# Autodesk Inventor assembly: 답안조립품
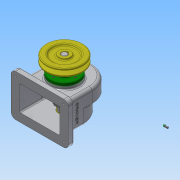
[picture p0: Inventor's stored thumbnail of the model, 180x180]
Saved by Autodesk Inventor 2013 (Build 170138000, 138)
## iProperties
Created: 2017-11
Part Number: 답안조립품
Document SubType Name: Assembly
Designer: Administrator
Author: Administrator
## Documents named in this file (14)
- C:\Users\Administrator\Desktop\471108V1012\답안조립품.iam
- C:\Users\Administrator\Desktop\471108V1012\본체.ipt
- C:\Users\Administrator\Desktop\471108V1012\V-벨트풀리.ipt
- C:\Users\Administrator\Desktop\471108V1012\뒤커버.ipt
- C:\Users\Administrator\Desktop\471108V1012\멈춤나사 - M4 x 10.ipt
- 멈춤나사 - M4 x 10.ipt
- C:\Users\Administrator\Desktop\471108V1012\베어링 6002.ipt
- C:\Users\Administrator\Desktop\471108V1012\볼트 M3 x 8.ipt
- C:\Users\Administrator\Desktop\471108V1012\스퍼기어.ipt
- C:\Users\Administrator\Desktop\471108V1012\앞커버.ipt
- C:\Users\Administrator\Desktop\471108V1012\오일 실 15 30 7.ipt
- C:\Users\Administrator\Desktop\471108V1012\축.ipt
- C:\Users\Administrator\Desktop\471108V1012\키 - 5 x 5 x 18.ipt
- C:\Users\Administrator\Desktop\471108V1012\키 - 6 x 6 x 22.ipt
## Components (1 placed, 1 different names)
1. V-벨트풀리:1
